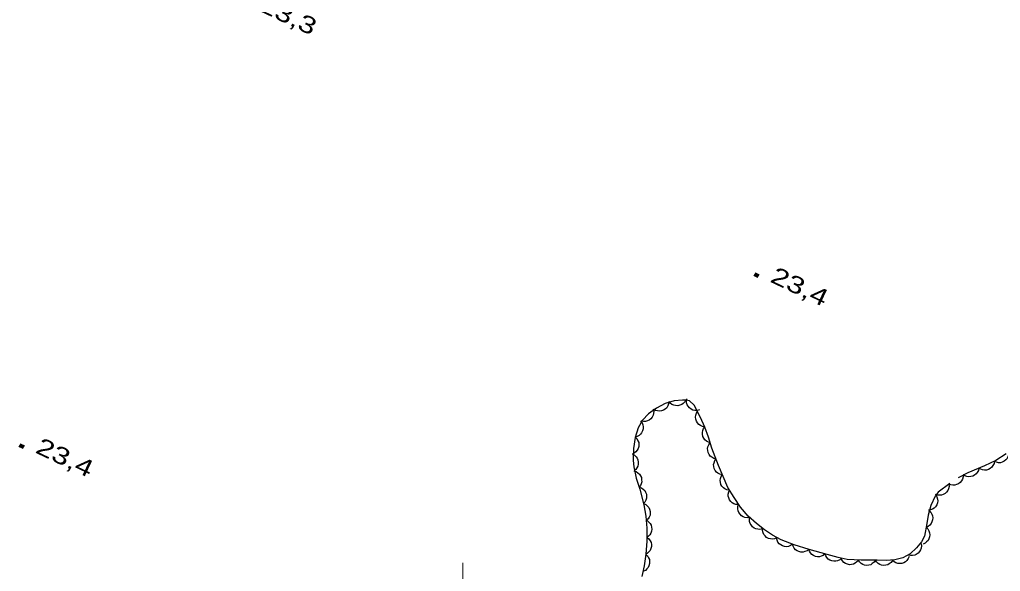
# Model space of a CAD drawing. Extents: x 356765 to 358572, y 5103174 to 5104650.
# Drawn here: x 357560.9 to 357647.4, y 5104004.2 to 5104052.9 of the extents above; entities that cross this region are included whole.
import ezdxf

# ---------------------------------------------------------------- set-up
doc = ezdxf.new("R2010")
doc.units = 0
doc.header["$LTSCALE"] = 0.6
doc.linetypes.add('DOT_DASHED', pattern=[7.7, 5, -1.2, 0.3, -1.2])
for name, color, linetype, lineweight in [('3', 7, 'Continuous', 140), ('44', 7, 'Continuous', 25), ('61', 7, 'Continuous', 13)]:
    doc.layers.add(name, color=color, linetype=linetype, lineweight=lineweight)

msp = doc.modelspace()

# ---------------------------------------------------------------- linework, layer by layer
at = {"layer": '3'}
for p, q in [((357625.73, 5104030.44), (357626.09, 5104030.27)), ((357560.91, 5104015.37), (357561.27, 5104015.2))]:
    msp.add_line(p, q, dxfattribs=at)
at = {"layer": '44', "linetype": 'DOT_DASHED'}
for points in [[(357642.97, 5104011.99), (357641.94, 5104011.21), (357641.67, 5104010.87), (357641.29, 5104010.05), (357641.06, 5104009.18), (357640.95, 5104008.45), (357640.74, 5104007.34), (357640.46, 5104006.84), (357640.03, 5104006.32), (357639.47, 5104005.8), (357638.82, 5104005.42), (357638.13, 5104005.25), (357637.36, 5104005.21), (357636.55, 5104005.22), (357635.15, 5104005.22), (357633.91, 5104005.29), (357633.13, 5104005.47), (357632.14, 5104005.74), (357630.56, 5104006.18), (357629.25, 5104006.57), (357628.08, 5104007.01), (357627.34, 5104007.43), (357626.62, 5104007.9), (357625.91, 5104008.46), (357625.18, 5104009.12), (357624.5, 5104009.9), (357623.93, 5104010.75), (357623.4, 5104011.63), (357622.96, 5104012.59), (357622.56, 5104013.58), (357621.98, 5104015.09), (357621.69, 5104016.07), (357621.36, 5104016.96), (357620.97, 5104017.8), (357620.42, 5104018.88), (357619.99, 5104019.26), (357619.72, 5104019.33), (357619.4, 5104019.34), (357618.66, 5104019.26), (357617.86, 5104019.04), (357617.08, 5104018.63), (357616.39, 5104018.13), (357615.86, 5104017.57), (357615.48, 5104016.88), (357615.2, 5104016.05), (357615.05, 5104015.08), (357615.02, 5104014.01), (357615.08, 5104013.46), (357615.3, 5104012.45), (357615.61, 5104011.5), (357615.98, 5104010.11), (357616.15, 5104009.12), (357616.23, 5104008.05), (357616.23, 5104006.91), (357616.14, 5104005.76), (357616.01, 5104004.72), (357616.01, 5104004.72), (357615.79, 5104003.8)], [(357647.94, 5104014.59), (357647.04, 5104014.01), (357646.02, 5104013.55), (357644.57, 5104012.94), (357643.71, 5104012.48)]]:
    msp.add_lwpolyline(points, dxfattribs=at)
at = {"layer": '44'}
for points in [[(357619.69, 5104019.37), (357619.59, 5104019.19), (357619.45, 5104019.04), (357619.32, 5104018.94), (357619.15, 5104018.88), (357618.97, 5104018.84), (357618.78, 5104018.85), (357618.62, 5104018.88), (357618.46, 5104018.96), (357618.31, 5104019.07), (357618.2, 5104019.21)], [(357620.88, 5104018.47), (357620.68, 5104018.42), (357620.48, 5104018.43), (357620.31, 5104018.46), (357620.16, 5104018.54), (357620.01, 5104018.65), (357619.89, 5104018.79), (357619.8, 5104018.93), (357619.75, 5104019.1), (357619.74, 5104019.29), (357619.76, 5104019.46)], [(357616.8, 5104018.56), (357616.85, 5104018.36), (357616.83, 5104018.16), (357616.8, 5104018), (357616.71, 5104017.84), (357616.6, 5104017.7), (357616.44, 5104017.58), (357616.3, 5104017.5), (357616.13, 5104017.46), (357615.95, 5104017.45), (357615.77, 5104017.47)], [(357618.18, 5104019.21), (357618.16, 5104019), (357618.08, 5104018.82), (357617.99, 5104018.67), (357617.86, 5104018.55), (357617.71, 5104018.45), (357617.53, 5104018.4), (357617.37, 5104018.36), (357617.19, 5104018.38), (357617.01, 5104018.43), (357616.85, 5104018.51)], [(357621.35, 5104016.98), (357621.15, 5104017.01), (357620.96, 5104017.1), (357620.83, 5104017.19), (357620.71, 5104017.33), (357620.62, 5104017.49), (357620.57, 5104017.67), (357620.54, 5104017.83), (357620.57, 5104018.01), (357620.63, 5104018.18), (357620.72, 5104018.34)], [(357615.69, 5104017.5), (357615.82, 5104017.34), (357615.89, 5104017.15), (357615.92, 5104016.98), (357615.91, 5104016.81), (357615.87, 5104016.63), (357615.78, 5104016.46), (357615.69, 5104016.33), (357615.55, 5104016.22), (357615.38, 5104016.13), (357615.21, 5104016.08)], [(357621.87, 5104015.57), (357621.67, 5104015.62), (357621.5, 5104015.73), (357621.37, 5104015.83), (357621.27, 5104015.97), (357621.19, 5104016.14), (357621.15, 5104016.33), (357621.14, 5104016.49), (357621.18, 5104016.66), (357621.25, 5104016.83), (357621.35, 5104016.98)], [(357615.2, 5104016.08), (357615.36, 5104015.94), (357615.46, 5104015.76), (357615.52, 5104015.61), (357615.54, 5104015.44), (357615.53, 5104015.25), (357615.47, 5104015.07), (357615.4, 5104014.92), (357615.28, 5104014.79), (357615.14, 5104014.68), (357614.98, 5104014.6)], [(357622.34, 5104014.15), (357622.14, 5104014.2), (357621.96, 5104014.3), (357621.83, 5104014.4), (357621.73, 5104014.54), (357621.65, 5104014.71), (357621.61, 5104014.89), (357621.59, 5104015.06), (357621.63, 5104015.23), (357621.7, 5104015.4), (357621.8, 5104015.55)], [(357614.96, 5104014.59), (357615.14, 5104014.49), (357615.29, 5104014.35), (357615.39, 5104014.22), (357615.45, 5104014.06), (357615.49, 5104013.87), (357615.47, 5104013.68), (357615.45, 5104013.52), (357615.37, 5104013.37), (357615.26, 5104013.22), (357615.12, 5104013.1)], [(357622.89, 5104012.75), (357622.69, 5104012.8), (357622.51, 5104012.9), (357622.38, 5104012.99), (357622.27, 5104013.14), (357622.19, 5104013.3), (357622.15, 5104013.49), (357622.13, 5104013.65), (357622.17, 5104013.82), (357622.23, 5104014), (357622.33, 5104014.14)], [(357648.17, 5104014.74), (357648.17, 5104014.53), (357648.1, 5104014.34), (357648.03, 5104014.19), (357647.91, 5104014.06), (357647.77, 5104013.95), (357647.59, 5104013.87), (357647.44, 5104013.82), (357647.26, 5104013.82), (357647.08, 5104013.86), (357646.91, 5104013.93)], [(357645.53, 5104013.34), (357645.49, 5104013.14), (357645.39, 5104012.96), (357645.29, 5104012.83), (357645.16, 5104012.72), (357644.99, 5104012.63), (357644.81, 5104012.59), (357644.64, 5104012.57), (357644.47, 5104012.6), (357644.3, 5104012.66), (357644.15, 5104012.76)], [(357646.9, 5104013.95), (357646.87, 5104013.74), (357646.77, 5104013.56), (357646.68, 5104013.42), (357646.54, 5104013.31), (357646.38, 5104013.22), (357646.2, 5104013.17), (357646.04, 5104013.15), (357645.86, 5104013.18), (357645.69, 5104013.24), (357645.53, 5104013.33)], [(357615.09, 5104013.09), (357615.29, 5104013.03), (357615.46, 5104012.92), (357615.59, 5104012.81), (357615.68, 5104012.67), (357615.76, 5104012.5), (357615.78, 5104012.31), (357615.79, 5104012.14), (357615.74, 5104011.97), (357615.67, 5104011.8), (357615.56, 5104011.66)], [(357623.51, 5104011.39), (357623.31, 5104011.42), (357623.12, 5104011.51), (357622.99, 5104011.6), (357622.87, 5104011.74), (357622.78, 5104011.9), (357622.73, 5104012.09), (357622.71, 5104012.25), (357622.73, 5104012.42), (357622.79, 5104012.6), (357622.89, 5104012.75)], [(357644.14, 5104012.76), (357644.14, 5104012.56), (357644.08, 5104012.36), (357644.01, 5104012.21), (357643.89, 5104012.08), (357643.74, 5104011.97), (357643.57, 5104011.89), (357643.41, 5104011.84), (357643.24, 5104011.84), (357643.05, 5104011.87), (357642.89, 5104011.94)], [(357615.57, 5104011.66), (357615.76, 5104011.6), (357615.93, 5104011.48), (357616.05, 5104011.36), (357616.13, 5104011.21), (357616.2, 5104011.04), (357616.21, 5104010.85), (357616.21, 5104010.68), (357616.16, 5104010.52), (357616.07, 5104010.35), (357615.95, 5104010.22)], [(357642.89, 5104011.93), (357642.9, 5104011.72), (357642.85, 5104011.52), (357642.79, 5104011.37), (357642.69, 5104011.23), (357642.55, 5104011.11), (357642.38, 5104011.02), (357642.23, 5104010.96), (357642.05, 5104010.95), (357641.87, 5104010.97), (357641.7, 5104011.03)], [(357624.31, 5104010.12), (357624.1, 5104010.13), (357623.91, 5104010.2), (357623.77, 5104010.27), (357623.64, 5104010.4), (357623.53, 5104010.54), (357623.46, 5104010.72), (357623.42, 5104010.88), (357623.42, 5104011.06), (357623.46, 5104011.24), (357623.54, 5104011.4)], [(357641.72, 5104010.99), (357641.83, 5104010.81), (357641.88, 5104010.61), (357641.9, 5104010.45), (357641.87, 5104010.27), (357641.81, 5104010.1), (357641.7, 5104009.94), (357641.59, 5104009.82), (357641.44, 5104009.72), (357641.27, 5104009.65), (357641.09, 5104009.63)], [(357615.96, 5104010.22), (357616.15, 5104010.13), (357616.3, 5104010), (357616.41, 5104009.87), (357616.49, 5104009.71), (357616.53, 5104009.53), (357616.53, 5104009.34), (357616.52, 5104009.18), (357616.45, 5104009.02), (357616.35, 5104008.86), (357616.22, 5104008.74)], [(357625.3, 5104008.98), (357625.09, 5104008.96), (357624.89, 5104008.99), (357624.73, 5104009.04), (357624.59, 5104009.14), (357624.46, 5104009.27), (357624.36, 5104009.43), (357624.29, 5104009.58), (357624.26, 5104009.75), (357624.27, 5104009.94), (357624.31, 5104010.11)], [(357626.43, 5104007.99), (357626.22, 5104007.94), (357626.02, 5104007.95), (357625.86, 5104007.98), (357625.7, 5104008.06), (357625.56, 5104008.18), (357625.44, 5104008.33), (357625.35, 5104008.46), (357625.31, 5104008.64), (357625.29, 5104008.82), (357625.31, 5104009)], [(357641.12, 5104009.61), (357641.28, 5104009.47), (357641.38, 5104009.29), (357641.45, 5104009.14), (357641.46, 5104008.96), (357641.45, 5104008.78), (357641.39, 5104008.6), (357641.33, 5104008.45), (357641.21, 5104008.32), (357641.06, 5104008.2), (357640.9, 5104008.12)], [(357616.23, 5104008.74), (357616.4, 5104008.62), (357616.53, 5104008.46), (357616.62, 5104008.32), (357616.66, 5104008.15), (357616.68, 5104007.97), (357616.65, 5104007.78), (357616.6, 5104007.62), (357616.5, 5104007.47), (357616.38, 5104007.34), (357616.23, 5104007.24)], [(357640.89, 5104008.13), (357641.04, 5104007.98), (357641.13, 5104007.8), (357641.19, 5104007.65), (357641.2, 5104007.47), (357641.19, 5104007.29), (357641.12, 5104007.11), (357641.05, 5104006.96), (357640.92, 5104006.83), (357640.78, 5104006.72), (357640.61, 5104006.65)], [(357616.26, 5104007.24), (357616.42, 5104007.11), (357616.53, 5104006.94), (357616.61, 5104006.79), (357616.64, 5104006.62), (357616.64, 5104006.43), (357616.6, 5104006.25), (357616.54, 5104006.09), (357616.43, 5104005.95), (357616.29, 5104005.83), (357616.14, 5104005.74)], [(357627.7, 5104007.19), (357627.51, 5104007.11), (357627.31, 5104007.09), (357627.14, 5104007.1), (357626.98, 5104007.15), (357626.81, 5104007.24), (357626.67, 5104007.37), (357626.56, 5104007.49), (357626.49, 5104007.65), (357626.45, 5104007.83), (357626.45, 5104008.01)], [(357629.09, 5104006.63), (357628.92, 5104006.51), (357628.73, 5104006.44), (357628.57, 5104006.41), (357628.39, 5104006.43), (357628.21, 5104006.48), (357628.05, 5104006.58), (357627.92, 5104006.67), (357627.81, 5104006.82), (357627.73, 5104006.98), (357627.69, 5104007.16)], [(357630.53, 5104006.19), (357630.37, 5104006.06), (357630.18, 5104005.98), (357630.02, 5104005.94), (357629.84, 5104005.94), (357629.66, 5104005.98), (357629.49, 5104006.06), (357629.35, 5104006.15), (357629.24, 5104006.29), (357629.14, 5104006.45), (357629.09, 5104006.62)], [(357640.43, 5104006.69), (357640.46, 5104006.49), (357640.43, 5104006.29), (357640.39, 5104006.13), (357640.3, 5104005.98), (357640.17, 5104005.84), (357640.01, 5104005.74), (357639.87, 5104005.66), (357639.69, 5104005.63), (357639.51, 5104005.63), (357639.33, 5104005.67)], [(357616.14, 5104005.74), (357616.29, 5104005.6), (357616.4, 5104005.43), (357616.47, 5104005.28), (357616.49, 5104005.11), (357616.49, 5104004.92), (357616.43, 5104004.74), (357616.37, 5104004.59), (357616.25, 5104004.45), (357616.11, 5104004.33), (357615.95, 5104004.25)], [(357631.97, 5104005.79), (357631.81, 5104005.65), (357631.63, 5104005.57), (357631.47, 5104005.53), (357631.29, 5104005.53), (357631.11, 5104005.56), (357630.94, 5104005.64), (357630.8, 5104005.73), (357630.68, 5104005.86), (357630.58, 5104006.02), (357630.53, 5104006.19)], [(357633.42, 5104005.39), (357633.26, 5104005.26), (357633.07, 5104005.17), (357632.92, 5104005.13), (357632.74, 5104005.13), (357632.56, 5104005.16), (357632.38, 5104005.24), (357632.24, 5104005.33), (357632.13, 5104005.46), (357632.03, 5104005.62), (357631.97, 5104005.79)], [(357639.37, 5104005.56), (357639.3, 5104005.36), (357639.17, 5104005.2), (357639.06, 5104005.08), (357638.9, 5104005), (357638.73, 5104004.94), (357638.54, 5104004.92), (357638.37, 5104004.93), (357638.21, 5104004.99), (357638.05, 5104005.08), (357637.91, 5104005.2)], [(357634.91, 5104005.23), (357634.78, 5104005.07), (357634.62, 5104004.95), (357634.47, 5104004.87), (357634.3, 5104004.84), (357634.11, 5104004.83), (357633.93, 5104004.87), (357633.77, 5104004.93), (357633.63, 5104005.03), (357633.5, 5104005.16), (357633.41, 5104005.32)], [(357636.41, 5104005.22), (357636.29, 5104005.05), (357636.13, 5104004.92), (357635.99, 5104004.83), (357635.82, 5104004.79), (357635.64, 5104004.77), (357635.45, 5104004.8), (357635.29, 5104004.85), (357635.14, 5104004.94), (357635.01, 5104005.07), (357634.91, 5104005.22)], [(357637.91, 5104005.2), (357637.79, 5104005.03), (357637.63, 5104004.91), (357637.49, 5104004.82), (357637.32, 5104004.78), (357637.13, 5104004.76), (357636.94, 5104004.8), (357636.79, 5104004.85), (357636.64, 5104004.94), (357636.51, 5104005.07), (357636.41, 5104005.22)]]:
    msp.add_lwpolyline(points, dxfattribs=at)
at = {"layer": '61'}
msp.add_line((357600, 5103995), (357600, 5104005), dxfattribs=at)

# ---------------------------------------------------------------- texts
at = {"layer": '3', "width": 1.35}
for s, p in [('23,3   ', (357581.9, 5104053.71)), ('23,4   ', (357627.03, 5104029.8)), ('23,4   ', (357562.21, 5104014.74))]:
    msp.add_text(s, height=1.5, rotation=334.619, dxfattribs=at).set_placement(p)

doc.saveas('drawing.dxf')
